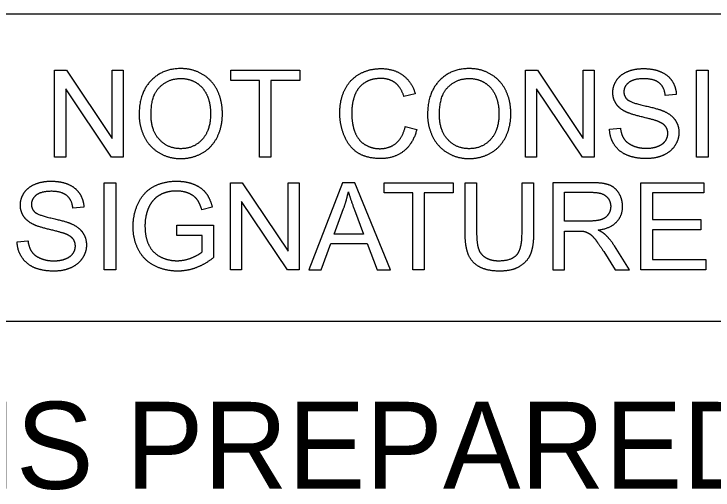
# Model space of a CAD drawing. Extents: x 1184121 to 1184397, y 1246506 to 1246661.
# Drawn here: x 1184349.023 to 1184353.092, y 1246605.521 to 1246608.295 of the extents above; entities that cross this region are included whole.
import ezdxf

# ---------------------------------------------------------------- set-up
doc = ezdxf.new("R2010")
doc.units = 0
doc.layers.add('Level_1', color=7, linetype='Continuous')
doc.layers.add('Sheet Plan CELL', color=7, linetype='Continuous')

msp = doc.modelspace()

# ---------------------------------------------------------------- linework, layer by layer
at = {"layer": 'Level_1'}
for p, q in [((1184344.3472, 1246608.2948), (1184358.4233, 1246608.2948)), ((1184351.359, 1246607.8287), (1184351.293, 1246607.8132)), ((1184352.8781, 1246607.825), (1184352.814, 1246607.82)), ((1184349.7515, 1246607.7077), (1184349.7515, 1246607.7077)), ((1184349.8206, 1246607.7068), (1184349.8206, 1246607.7068)), ((1184351.4301, 1246607.7077), (1184351.4301, 1246607.7077)), ((1184351.4992, 1246607.7068), (1184351.4992, 1246607.7068)), ((1184351.3003, 1246607.6387), (1184351.3675, 1246607.6218)), ((1184352.4895, 1246607.6238), (1184352.5529, 1246607.6292)), ((1184349.4298, 1246607.1692), (1184349.3656, 1246607.1642)), ((1184350.1772, 1246607.17), (1184350.1168, 1246607.1534)), ((1184349.0412, 1246606.968), (1184349.1045, 1246606.9734)), ((1184358.4233, 1246606.5021), (1184344.3472, 1246606.5021))]:
    msp.add_line(p, q, dxfattribs=at)
for points in [[(1184349.2598, 1246607.4608), (1184349.2598, 1246607.9676), (1184349.3284, 1246607.9676), (1184349.5951, 1246607.5696), (1184349.5951, 1246607.9676), (1184349.6592, 1246607.9676), (1184349.6592, 1246607.4608), (1184349.5906, 1246607.4608), (1184349.3239, 1246607.8588), (1184349.3239, 1246607.4608)], [(1184350.4514, 1246607.4608), (1184350.4514, 1246607.9077), (1184350.2845, 1246607.9077), (1184350.2845, 1246607.9676), (1184350.6862, 1246607.9676), (1184350.6862, 1246607.9077), (1184350.5186, 1246607.9077), (1184350.5186, 1246607.4608)], [(1184352.0006, 1246607.4608), (1184352.0006, 1246607.9676), (1184352.0692, 1246607.9676), (1184352.3358, 1246607.5696), (1184352.3358, 1246607.9676), (1184352.3999, 1246607.9676), (1184352.3999, 1246607.4608), (1184352.3313, 1246607.4608), (1184352.0647, 1246607.8588), (1184352.0647, 1246607.4608)], [(1184352.9963, 1246607.4608), (1184352.9963, 1246607.9676), (1184353.0635, 1246607.9676), (1184353.0635, 1246607.4608)], [(1184349.5479, 1246606.805), (1184349.5479, 1246607.3117), (1184349.6151, 1246607.3117), (1184349.6151, 1246606.805)], [(1184350.2833, 1246606.805), (1184350.2833, 1246607.3117), (1184350.352, 1246607.3117), (1184350.6186, 1246606.9137), (1184350.6186, 1246607.3117), (1184350.6827, 1246607.3117), (1184350.6827, 1246606.805), (1184350.6141, 1246606.805), (1184350.3475, 1246607.203), (1184350.3475, 1246606.805)], [(1184350.7398, 1246606.805), (1184350.8109, 1246606.805), (1184350.8665, 1246606.9583), (1184351.079, 1246606.9583), (1184351.1377, 1246606.805), (1184351.2141, 1246606.805), (1184351.0071, 1246607.3117), (1184350.9346, 1246607.3117)], [(1184351.344, 1246606.805), (1184351.344, 1246607.2519), (1184351.1771, 1246607.2519), (1184351.1771, 1246607.3117), (1184351.5788, 1246607.3117), (1184351.5788, 1246607.2519), (1184351.4112, 1246607.2519), (1184351.4112, 1246606.805)], [(1184352.6718, 1246606.805), (1184352.6718, 1246607.3117), (1184353.0388, 1246607.3117), (1184353.0388, 1246607.2519), (1184352.7391, 1246607.2519), (1184352.7391, 1246607.097), (1184353.0198, 1246607.097), (1184353.0198, 1246607.0371), (1184352.7391, 1246607.0371), (1184352.7391, 1246606.8649), (1184353.0504, 1246606.8649), (1184353.0504, 1246606.805)]]:
    msp.add_lwpolyline(points, close=True, dxfattribs=at)
for points in [[(1184351.6487, 1246607.019), (1184351.6487, 1246607.3117), (1184351.7159, 1246607.3117), (1184351.7159, 1246607.0195)], [(1184351.9801, 1246607.0195), (1184351.9801, 1246607.3117), (1184352.0473, 1246607.3117), (1184352.0473, 1246607.019)], [(1184352.3849, 1246607.3117), (1184352.1601, 1246607.3117), (1184352.1601, 1246606.805), (1184352.2273, 1246606.805), (1184352.2273, 1246607.0302), (1184352.305, 1246607.0302)], [(1184352.3714, 1246607.0881), (1184352.2273, 1246607.0881), (1184352.2273, 1246607.2557), (1184352.3876, 1246607.2557)], [(1184351.0048, 1246607.1535), (1184351.058, 1246607.0128), (1184350.8859, 1246607.0128), (1184350.9419, 1246607.1616)], [(1184350.1192, 1246606.9095), (1184350.1192, 1246607.0035), (1184349.9705, 1246607.0035), (1184349.9705, 1246607.0634), (1184350.1849, 1246607.0634), (1184350.1849, 1246606.8756)], [(1184352.4554, 1246606.9104), (1184352.5224, 1246606.805), (1184352.6062, 1246606.805), (1184352.5185, 1246606.9429)]]:
    msp.add_lwpolyline(points, dxfattribs=at)
for points in [[(1184349.9942, 1246607.9765), (1184349.887, 1246607.9765), (1184349.8193, 1246607.9051)], [(1184350.1207, 1246607.9429), (1184350.0644, 1246607.9765), (1184349.9942, 1246607.9765)], [(1184351.0358, 1246607.9459), (1184351.0917, 1246607.9765), (1184351.1588, 1246607.9765)], [(1184351.1588, 1246607.9765), (1184351.2349, 1246607.9765), (1184351.2867, 1246607.9377)], [(1184351.6728, 1246607.9765), (1184351.5656, 1246607.9765), (1184351.4979, 1246607.9051)], [(1184351.7993, 1246607.9429), (1184351.743, 1246607.9765), (1184351.6728, 1246607.9765)], [(1184352.5303, 1246607.9085), (1184352.5521, 1246607.9419), (1184352.594, 1246607.9592)], [(1184352.594, 1246607.9592), (1184352.6359, 1246607.9765), (1184352.6872, 1246607.9765)], [(1184352.6872, 1246607.9765), (1184352.7437, 1246607.9765), (1184352.7868, 1246607.9583)], [(1184352.7868, 1246607.9583), (1184352.8299, 1246607.9402), (1184352.8532, 1246607.9049)], [(1184349.872, 1246607.87), (1184349.9233, 1246607.9189), (1184349.9945, 1246607.9189)], [(1184349.9945, 1246607.9189), (1184350.0447, 1246607.9189), (1184350.085, 1246607.8935)], [(1184350.2067, 1246607.8495), (1184350.1771, 1246607.9094), (1184350.1207, 1246607.9429)], [(1184350.9497, 1246607.8563), (1184350.98, 1246607.9153), (1184351.0358, 1246607.9459)], [(1184351.1574, 1246607.9189), (1184351.0989, 1246607.9189), (1184351.0597, 1246607.8909)], [(1184351.2418, 1246607.8937), (1184351.2082, 1246607.9189), (1184351.1574, 1246607.9189)], [(1184351.2867, 1246607.9377), (1184351.3386, 1246607.899), (1184351.359, 1246607.8287)], [(1184351.5506, 1246607.87), (1184351.6019, 1246607.9189), (1184351.6731, 1246607.9189)], [(1184351.6731, 1246607.9189), (1184351.7233, 1246607.9189), (1184351.7636, 1246607.8935)], [(1184351.8853, 1246607.8495), (1184351.8557, 1246607.9094), (1184351.7993, 1246607.9429)], [(1184352.5085, 1246607.8367), (1184352.5085, 1246607.8751), (1184352.5303, 1246607.9085)], [(1184352.69, 1246607.9174), (1184352.6289, 1246607.9174), (1184352.6009, 1246607.895)], [(1184352.7787, 1246607.8928), (1184352.7487, 1246607.9174), (1184352.69, 1246607.9174)], [(1184349.8193, 1246607.9051), (1184349.7515, 1246607.8338), (1184349.7515, 1246607.7077)], [(1184349.8206, 1246607.7068), (1184349.8206, 1246607.8211), (1184349.872, 1246607.87)], [(1184350.085, 1246607.8935), (1184350.1252, 1246607.8681), (1184350.1462, 1246607.822)], [(1184351.0597, 1246607.8909), (1184351.0204, 1246607.8629), (1184351.0045, 1246607.8158)], [(1184351.293, 1246607.8132), (1184351.2753, 1246607.8685), (1184351.2418, 1246607.8937)], [(1184351.4979, 1246607.9051), (1184351.4301, 1246607.8338), (1184351.4301, 1246607.7077)], [(1184351.4992, 1246607.7068), (1184351.4992, 1246607.8211), (1184351.5506, 1246607.87)], [(1184351.7636, 1246607.8935), (1184351.8038, 1246607.8681), (1184351.8248, 1246607.822)], [(1184352.6009, 1246607.895), (1184352.573, 1246607.8727), (1184352.573, 1246607.8412)], [(1184352.814, 1246607.82), (1184352.8088, 1246607.8682), (1184352.7787, 1246607.8928)], [(1184352.8532, 1246607.9049), (1184352.8764, 1246607.8696), (1184352.8781, 1246607.825)], [(1184350.2362, 1246607.7135), (1184350.2362, 1246607.7895), (1184350.2067, 1246607.8495)], [(1184350.9195, 1246607.7182), (1184350.9195, 1246607.7974), (1184350.9497, 1246607.8563)], [(1184351.9148, 1246607.7135), (1184351.9148, 1246607.7895), (1184351.8853, 1246607.8495)], [(1184352.5263, 1246607.7736), (1184352.5085, 1246607.8018), (1184352.5085, 1246607.8367)], [(1184352.573, 1246607.8412), (1184352.573, 1246607.8139), (1184352.5928, 1246607.7963)], [(1184350.1462, 1246607.822), (1184350.1671, 1246607.7759), (1184350.1671, 1246607.714)], [(1184351.0045, 1246607.8158), (1184350.9886, 1246607.7686), (1184350.9886, 1246607.7185)], [(1184351.8248, 1246607.822), (1184351.8457, 1246607.7759), (1184351.8457, 1246607.714)], [(1184352.5928, 1246607.7963), (1184352.6122, 1246607.7786), (1184352.6943, 1246607.7601)], [(1184352.5804, 1246607.7264), (1184352.5441, 1246607.7454), (1184352.5263, 1246607.7736)], [(1184352.6943, 1246607.7601), (1184352.7765, 1246607.7416), (1184352.8069, 1246607.7278)], [(1184349.7515, 1246607.7077), (1184349.7515, 1246607.641), (1184349.7805, 1246607.5812)], [(1184349.8699, 1246607.5626), (1184349.8206, 1246607.6152), (1184349.8206, 1246607.7068)], [(1184350.1671, 1246607.714), (1184350.1671, 1246607.6163), (1184350.1182, 1246607.5631)], [(1184350.2051, 1246607.5757), (1184350.2362, 1246607.6365), (1184350.2362, 1246607.7135)], [(1184350.9463, 1246607.5823), (1184350.9195, 1246607.6456), (1184350.9195, 1246607.7182)], [(1184350.9886, 1246607.7185), (1184350.9886, 1246607.6539), (1184351.0074, 1246607.6057)], [(1184351.4301, 1246607.7077), (1184351.4301, 1246607.641), (1184351.4591, 1246607.5812)], [(1184351.5485, 1246607.5626), (1184351.4992, 1246607.6152), (1184351.4992, 1246607.7068)], [(1184351.8457, 1246607.714), (1184351.8457, 1246607.6163), (1184351.7968, 1246607.5631)], [(1184351.8837, 1246607.5757), (1184351.9148, 1246607.6365), (1184351.9148, 1246607.7135)], [(1184352.6785, 1246607.6947), (1184352.6084, 1246607.7115), (1184352.5804, 1246607.7264)], [(1184352.8069, 1246607.7278), (1184352.851, 1246607.7074), (1184352.8721, 1246607.6761)], [(1184352.7692, 1246607.67), (1184352.7487, 1246607.6779), (1184352.6785, 1246607.6947)], [(1184352.8149, 1246607.64), (1184352.8011, 1246607.6579), (1184352.7692, 1246607.67)], [(1184352.8721, 1246607.6761), (1184352.8932, 1246607.6448), (1184352.8932, 1246607.604)], [(1184351.2474, 1246607.5423), (1184351.2865, 1246607.5748), (1184351.3003, 1246607.6387)], [(1184352.5174, 1246607.5327), (1184352.4909, 1246607.573), (1184352.4895, 1246607.6238)], [(1184352.5529, 1246607.6292), (1184352.5574, 1246607.5911), (1184352.5738, 1246607.5667)], [(1184352.8287, 1246607.5984), (1184352.8287, 1246607.6222), (1184352.8149, 1246607.64)], [(1184351.0244, 1246607.4857), (1184350.9731, 1246607.5191), (1184350.9463, 1246607.5823)], [(1184351.0074, 1246607.6057), (1184351.0263, 1246607.5576), (1184351.066, 1246607.5337)], [(1184351.3675, 1246607.6218), (1184351.3464, 1246607.5391), (1184351.2916, 1246607.4957)], [(1184352.8143, 1246607.555), (1184352.8287, 1246607.5749), (1184352.8287, 1246607.5984)], [(1184352.8932, 1246607.604), (1184352.8932, 1246607.5636), (1184352.87, 1246607.5278)], [(1184349.7805, 1246607.5812), (1184349.8096, 1246607.5214), (1184349.8659, 1246607.4869)], [(1184349.9935, 1246607.5099), (1184349.9192, 1246607.5099), (1184349.8699, 1246607.5626)], [(1184350.1182, 1246607.5631), (1184350.0692, 1246607.5099), (1184349.9935, 1246607.5099)], [(1184350.1169, 1246607.4836), (1184350.174, 1246607.5149), (1184350.2051, 1246607.5757)], [(1184351.1521, 1246607.5099), (1184351.2084, 1246607.5099), (1184351.2474, 1246607.5423)], [(1184351.4591, 1246607.5812), (1184351.4882, 1246607.5214), (1184351.5445, 1246607.4869)], [(1184351.6721, 1246607.5099), (1184351.5978, 1246607.5099), (1184351.5485, 1246607.5626)], [(1184351.7968, 1246607.5631), (1184351.7478, 1246607.5099), (1184351.6721, 1246607.5099)], [(1184351.7955, 1246607.4836), (1184351.8526, 1246607.5149), (1184351.8837, 1246607.5757)], [(1184352.5738, 1246607.5667), (1184352.5903, 1246607.5423), (1184352.6249, 1246607.5273)], [(1184352.7705, 1246607.5236), (1184352.7999, 1246607.535), (1184352.8143, 1246607.555)], [(1184351.066, 1246607.5337), (1184351.1058, 1246607.5099), (1184351.1521, 1246607.5099)], [(1184352.5904, 1246607.4724), (1184352.5438, 1246607.4924), (1184352.5174, 1246607.5327)], [(1184352.6249, 1246607.5273), (1184352.6595, 1246607.5122), (1184352.7027, 1246607.5122)], [(1184352.7027, 1246607.5122), (1184352.7411, 1246607.5122), (1184352.7705, 1246607.5236)], [(1184352.87, 1246607.5278), (1184352.8468, 1246607.4921), (1184352.8034, 1246607.4722)], [(1184349.8659, 1246607.4869), (1184349.9223, 1246607.4523), (1184349.9939, 1246607.4523)], [(1184349.9939, 1246607.4523), (1184350.0599, 1246607.4523), (1184350.1169, 1246607.4836)], [(1184351.1577, 1246607.4523), (1184351.0757, 1246607.4523), (1184351.0244, 1246607.4857)], [(1184351.2916, 1246607.4957), (1184351.2368, 1246607.4523), (1184351.1577, 1246607.4523)], [(1184351.5445, 1246607.4869), (1184351.6009, 1246607.4523), (1184351.6725, 1246607.4523)], [(1184351.6725, 1246607.4523), (1184351.7385, 1246607.4523), (1184351.7955, 1246607.4836)], [(1184352.7057, 1246607.4523), (1184352.6369, 1246607.4523), (1184352.5904, 1246607.4724)], [(1184352.8034, 1246607.4722), (1184352.76, 1246607.4523), (1184352.7057, 1246607.4523)], [(1184349.0819, 1246607.2526), (1184349.1038, 1246607.286), (1184349.1457, 1246607.3033)], [(1184349.1457, 1246607.3033), (1184349.1876, 1246607.3206), (1184349.2389, 1246607.3206)], [(1184349.2389, 1246607.3206), (1184349.2953, 1246607.3206), (1184349.3385, 1246607.3025)], [(1184349.3385, 1246607.3025), (1184349.3816, 1246607.2843), (1184349.4048, 1246607.2491)], [(1184349.8362, 1246607.2895), (1184349.8943, 1246607.3206), (1184349.9699, 1246607.3206)], [(1184349.9699, 1246607.3206), (1184350.0249, 1246607.3206), (1184350.0693, 1246607.3028)], [(1184350.0693, 1246607.3028), (1184350.1137, 1246607.2849), (1184350.1389, 1246607.2531)], [(1184352.4878, 1246607.2981), (1184352.4526, 1246607.3117), (1184352.3849, 1246607.3117)], [(1184352.5442, 1246607.2499), (1184352.5231, 1246607.2844), (1184352.4878, 1246607.2981)], [(1184349.2417, 1246607.2615), (1184349.1805, 1246607.2615), (1184349.1526, 1246607.2392)], [(1184349.3304, 1246607.2369), (1184349.3003, 1246607.2615), (1184349.2417, 1246607.2615)], [(1184349.7473, 1246607.1943), (1184349.7782, 1246607.2584), (1184349.8362, 1246607.2895)], [(1184349.9703, 1246607.2631), (1184349.9244, 1246607.2631), (1184349.8908, 1246607.2491)], [(1184350.0401, 1246607.2497), (1184350.0086, 1246607.2631), (1184349.9703, 1246607.2631)], [(1184350.9419, 1246607.1616), (1184350.9591, 1246607.2098), (1184350.9691, 1246607.2584)], [(1184350.9691, 1246607.2584), (1184350.981, 1246607.2176), (1184351.0048, 1246607.1535)], [(1184349.0601, 1246607.1809), (1184349.0601, 1246607.2193), (1184349.0819, 1246607.2526)], [(1184349.1526, 1246607.2392), (1184349.1246, 1246607.2169), (1184349.1246, 1246607.1854)], [(1184349.3656, 1246607.1642), (1184349.3604, 1246607.2123), (1184349.3304, 1246607.2369)], [(1184349.4048, 1246607.2491), (1184349.428, 1246607.2138), (1184349.4298, 1246607.1692)], [(1184349.8908, 1246607.2491), (1184349.8573, 1246607.2351), (1184349.8368, 1246607.2123)], [(1184350.0884, 1246607.2143), (1184350.0715, 1246607.2364), (1184350.0401, 1246607.2497)], [(1184350.1389, 1246607.2531), (1184350.1641, 1246607.2212), (1184350.1772, 1246607.17)], [(1184352.3876, 1246607.2557), (1184352.4439, 1246607.2557), (1184352.47, 1246607.2326)], [(1184352.47, 1246607.2326), (1184352.4961, 1246607.2094), (1184352.4961, 1246607.1735)], [(1184352.5652, 1246607.1735), (1184352.5652, 1246607.2153), (1184352.5442, 1246607.2499)], [(1184349.0779, 1246607.1177), (1184349.0601, 1246607.1459), (1184349.0601, 1246607.1809)], [(1184349.1246, 1246607.1854), (1184349.1246, 1246607.1581), (1184349.1444, 1246607.1404)], [(1184349.7163, 1246607.0561), (1184349.7163, 1246607.1301), (1184349.7473, 1246607.1943)], [(1184349.8368, 1246607.2123), (1184349.8162, 1246607.1895), (1184349.8048, 1246607.1622)], [(1184350.1168, 1246607.1534), (1184350.1054, 1246607.1921), (1184350.0884, 1246607.2143)], [(1184349.1444, 1246607.1404), (1184349.1639, 1246607.1228), (1184349.246, 1246607.1043)], [(1184349.8048, 1246607.1622), (1184349.7855, 1246607.1152), (1184349.7855, 1246607.0603)], [(1184352.4961, 1246607.1735), (1184352.4961, 1246607.1489), (1184352.4826, 1246607.128)], [(1184352.5303, 1246607.0826), (1184352.5652, 1246607.1196), (1184352.5652, 1246607.1735)], [(1184349.132, 1246607.0705), (1184349.0957, 1246607.0895), (1184349.0779, 1246607.1177)], [(1184349.246, 1246607.1043), (1184349.3281, 1246607.0858), (1184349.3585, 1246607.0719)], [(1184352.4433, 1246607.0976), (1184352.4173, 1246607.0881), (1184352.3714, 1246607.0881)], [(1184352.4826, 1246607.128), (1184352.4692, 1246607.1071), (1184352.4433, 1246607.0976)], [(1184349.2302, 1246607.0389), (1184349.16, 1246607.0556), (1184349.132, 1246607.0705)], [(1184349.3585, 1246607.0719), (1184349.4027, 1246607.0515), (1184349.4238, 1246607.0203)], [(1184349.7474, 1246606.921), (1184349.7163, 1246606.9815), (1184349.7163, 1246607.0561)], [(1184349.7855, 1246607.0603), (1184349.7855, 1246606.9926), (1184349.8088, 1246606.947)], [(1184352.4225, 1246607.0356), (1184352.4954, 1246607.0456), (1184352.5303, 1246607.0826)], [(1184349.3208, 1246607.0141), (1184349.3003, 1246607.0221), (1184349.2302, 1246607.0389)], [(1184349.3666, 1246606.9842), (1184349.3528, 1246607.002), (1184349.3208, 1246607.0141)], [(1184349.4238, 1246607.0203), (1184349.4448, 1246606.989), (1184349.4448, 1246606.9482)], [(1184351.6681, 1246606.892), (1184351.6487, 1246606.9385), (1184351.6487, 1246607.019)], [(1184351.7159, 1246607.0195), (1184351.7159, 1246606.9535), (1184351.7282, 1246606.9222)], [(1184351.9487, 1246606.8906), (1184351.9801, 1246606.9241), (1184351.9801, 1246607.0195)], [(1184352.0473, 1246607.019), (1184352.0473, 1246606.9427), (1184352.03, 1246606.8977)], [(1184352.305, 1246607.0302), (1184352.331, 1246607.0302), (1184352.3424, 1246607.0277)], [(1184352.3424, 1246607.0277), (1184352.3579, 1246607.0239), (1184352.3729, 1246607.0142)], [(1184352.3729, 1246607.0142), (1184352.388, 1246607.0045), (1184352.407, 1246606.9803)], [(1184352.463, 1246607.0103), (1184352.4491, 1246607.0228), (1184352.4225, 1246607.0356)], [(1184349.1045, 1246606.9734), (1184349.109, 1246606.9353), (1184349.1255, 1246606.9109)], [(1184349.3803, 1246606.9425), (1184349.3803, 1246606.9664), (1184349.3666, 1246606.9842)], [(1184352.407, 1246606.9803), (1184352.426, 1246606.9561), (1184352.4554, 1246606.9104)], [(1184352.5185, 1246606.9429), (1184352.4923, 1246606.9834), (1184352.463, 1246607.0103)], [(1184349.069, 1246606.8769), (1184349.0426, 1246606.9172), (1184349.0412, 1246606.968)], [(1184349.366, 1246606.8991), (1184349.3803, 1246606.919), (1184349.3803, 1246606.9425)], [(1184349.4448, 1246606.9482), (1184349.4448, 1246606.9078), (1184349.4216, 1246606.872)], [(1184349.8088, 1246606.947), (1184349.8321, 1246606.9013), (1184349.8767, 1246606.8792)], [(1184349.1255, 1246606.9109), (1184349.1419, 1246606.8865), (1184349.1765, 1246606.8714)], [(1184349.3222, 1246606.8678), (1184349.3516, 1246606.8792), (1184349.366, 1246606.8991)], [(1184349.8395, 1246606.8285), (1184349.7785, 1246606.8604), (1184349.7474, 1246606.921)], [(1184350.0563, 1246606.8738), (1184350.0978, 1246606.8905), (1184350.1192, 1246606.9095)], [(1184351.7327, 1246606.821), (1184351.6874, 1246606.8456), (1184351.6681, 1246606.892)], [(1184351.7282, 1246606.9222), (1184351.7404, 1246606.891), (1184351.7703, 1246606.8741)], [(1184351.8433, 1246606.8571), (1184351.9172, 1246606.8571), (1184351.9487, 1246606.8906)], [(1184352.03, 1246606.8977), (1184352.0127, 1246606.8528), (1184351.9676, 1246606.8247)], [(1184349.142, 1246606.8165), (1184349.0955, 1246606.8366), (1184349.069, 1246606.8769)], [(1184349.1765, 1246606.8714), (1184349.2111, 1246606.8564), (1184349.2544, 1246606.8564)], [(1184349.2544, 1246606.8564), (1184349.2928, 1246606.8564), (1184349.3222, 1246606.8678)], [(1184349.4216, 1246606.872), (1184349.3985, 1246606.8362), (1184349.3551, 1246606.8164)], [(1184349.8767, 1246606.8792), (1184349.9212, 1246606.8571), (1184349.9713, 1246606.8571)], [(1184349.9713, 1246606.8571), (1184350.0149, 1246606.8571), (1184350.0563, 1246606.8738)], [(1184350.1849, 1246606.8756), (1184350.1354, 1246606.8362), (1184350.0829, 1246606.8163)], [(1184351.7703, 1246606.8741), (1184351.8002, 1246606.8571), (1184351.8433, 1246606.8571)], [(1184349.2574, 1246606.7965), (1184349.1885, 1246606.7965), (1184349.142, 1246606.8165)], [(1184349.3551, 1246606.8164), (1184349.3117, 1246606.7965), (1184349.2574, 1246606.7965)], [(1184349.9751, 1246606.7965), (1184349.9005, 1246606.7965), (1184349.8395, 1246606.8285)], [(1184350.0829, 1246606.8163), (1184350.0304, 1246606.7965), (1184349.9751, 1246606.7965)], [(1184351.8492, 1246606.7965), (1184351.778, 1246606.7965), (1184351.7327, 1246606.821)], [(1184351.9676, 1246606.8247), (1184351.9225, 1246606.7965), (1184351.8492, 1246606.7965)]]:
    msp.add_open_spline(points, degree=2, dxfattribs=at)
at = {"layer": 'Sheet Plan CELL'}
msp.add_line((1184358.422, 1246606.5021), (1184344.3472, 1246606.5021), dxfattribs=at)

# ---------------------------------------------------------------- texts
msp.add_text('PLANS PREPARED BY:', height=0.506702, rotation=0, dxfattribs=at).set_placement((1184347.2644, 1246605.5283))

doc.saveas('drawing.dxf')
